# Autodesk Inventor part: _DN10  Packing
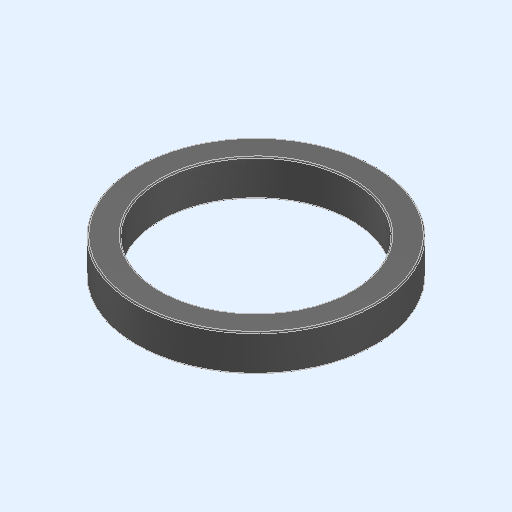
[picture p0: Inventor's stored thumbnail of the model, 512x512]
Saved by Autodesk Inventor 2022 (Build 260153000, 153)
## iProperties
Created: 2021-12
Part Number: _DN10  Packing
Material: Generico
Document SubType Name: Modeling
Designer: admin
Density: 1 g/cm^3
Appearance: Default
Author: admin
Revision Number: NONE
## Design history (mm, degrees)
feature "_DN10  Packing"
node "Solido1"
